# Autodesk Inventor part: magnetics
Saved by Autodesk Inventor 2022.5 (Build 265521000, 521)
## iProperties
Created: 2024-12
Part Number: magnetics
Material: Generic
Document SubType Name: Modeling
Designer: AdminForWorker
Density: 1 g/cm^3
Appearance: Default
Title: magnetics
Author: AdminForWorker
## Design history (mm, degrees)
feature "Body1"
feature "Body2"
body "Solid1"
body "Solid2"
